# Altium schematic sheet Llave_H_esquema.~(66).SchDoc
size A4
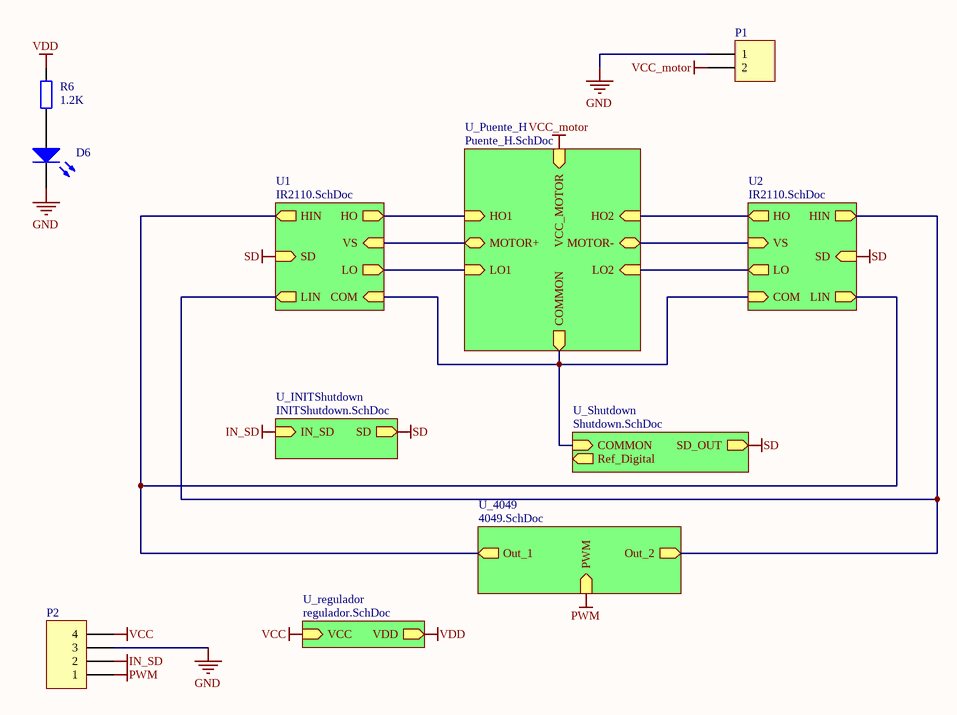
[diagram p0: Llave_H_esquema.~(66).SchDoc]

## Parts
D6  LED0  [CAPPR2.5-6.3X5]  (value not drawn)
P1  Header 2  [pwheader1x2]  (value not drawn)
P2  Header 4  [HDR1X5]  (value not drawn)
R6  1.2k  [AXIAL-0.3]

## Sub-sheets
U1 = IR2110.SchDoc: SD (in), HIN (out), LIN (out), HO (out), LO (out), VS (in), COM (in)
U2 = IR2110.SchDoc: SD (in), HIN (out), LIN (out), HO (out), LO (out), VS (in), COM (in)
U_4049 = 4049.SchDoc: PWM (in), Out_1 (out), Out_2 (out)
U_INITShutdown = INITShutdown.SchDoc: IN_SD (in), SD (out)
U_Puente_H = Puente_H.SchDoc: HO1 (in), LO1 (in), HO2 (in), LO2 (in), MOTOR+ (bidir), MOTOR- (bidir), VCC_MOTOR (in), COMMON (out)
U_regulador = regulador.SchDoc: VCC (in), VDD (out)
U_Shutdown = Shutdown.SchDoc: COMMON (in), SD_OUT (out), Ref_Digital (out)

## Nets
GND: D6.2(K) P1.1 P2.3
IN_SD: P2.2 ; sheet U_INITShutdown/IN_SD
PWM: P2.1 ; sheet U_4049/PWM
SD: sheet U1/SD, sheet U2/SD, sheet U_INITShutdown/SD, sheet U_Shutdown/SD_OUT
VCC: P2.4 ; sheet U_regulador/VCC
VCC_motor: P1.2 ; sheet U_Puente_H/VCC_MOTOR
VDD: R6.2 ; sheet U_regulador/VDD
NetD6_1: D6.1(A) R6.1
(unnamed): sheet U1/HIN, sheet U2/LIN, sheet U_4049/Out_1
(unnamed): sheet U1/LIN, sheet U2/HIN, sheet U_4049/Out_2  [a separate net that carries the same name]
(unnamed): sheet U1/HO, sheet U_Puente_H/HO1  [a separate net that carries the same name]
(unnamed): sheet U1/LO, sheet U_Puente_H/LO1  [a separate net that carries the same name]
(unnamed): sheet U1/VS, sheet U_Puente_H/MOTOR+  [a separate net that carries the same name]
(unnamed): sheet U1/COM, sheet U2/COM, sheet U_Puente_H/COMMON, sheet U_Shutdown/COMMON  [a separate net that carries the same name]
(unnamed): sheet U2/HO, sheet U_Puente_H/HO2  [a separate net that carries the same name]
(unnamed): sheet U2/LO, sheet U_Puente_H/LO2  [a separate net that carries the same name]
(unnamed): sheet U2/VS, sheet U_Puente_H/MOTOR-  [a separate net that carries the same name]

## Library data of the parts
D6 = LED0: Typical INFRARED GaAs LED
P1 = Header 2: Header, 2-Pin; value: pw1x2
P2 = Header 4: Header, 4-Pin; value: hdr1x5
R6 = Res2: Resistor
